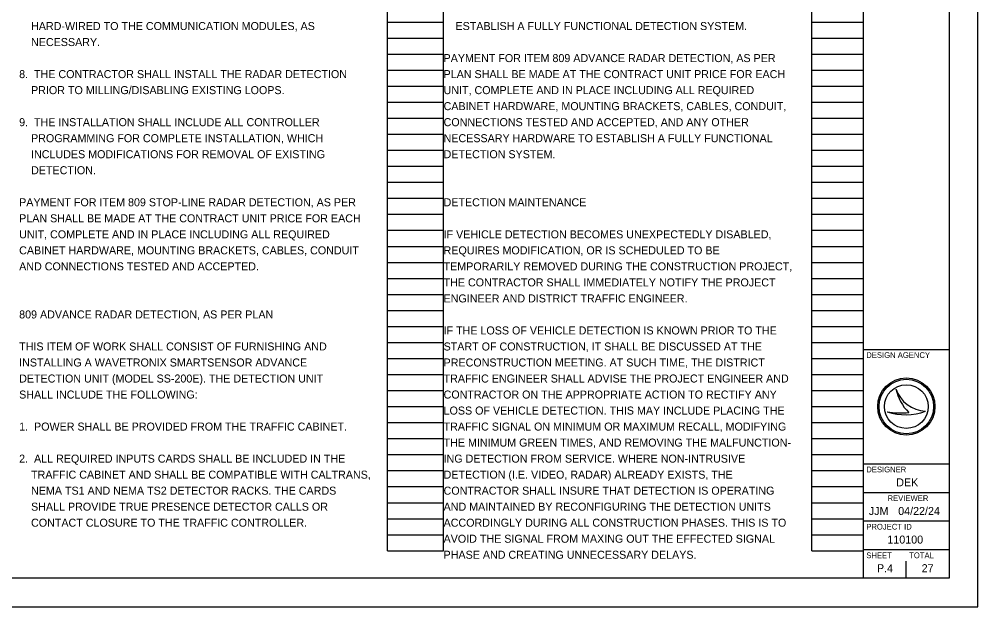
# Model space of a CAD drawing. Extents: x 0 to 34, y 0 to 22.
# Drawn here: x 17.24 to 34, y 0 to 10.27 of the extents above; entities that cross this region are included whole.
import ezdxf

# ---------------------------------------------------------------- set-up
doc = ezdxf.new("R2010")
doc.units = 0
for name, color, linetype in [('SH_Border', 7, 'Continuous'), ('SH_Cut_Line', 7, 'Continuous'), ('SH_Data', 7, 'Continuous'), ('SH_Text', 7, 'Continuous')]:
    doc.layers.add(name, color=color, linetype=linetype)

msp = doc.modelspace()

# ---------------------------------------------------------------- linework, layer by layer
at = {"layer": 'SH_Border'}
for p, q in [((32, 0.5), (32, 21.5)), ((32, 4.5), (33.5, 4.5)), ((32, 2.5), (33.5, 2.5)), ((32, 2), (33.5, 2)), ((32, 1.5), (33.5, 1.5)), ((32, 1), (33.5, 1))]:
    msp.add_line(p, q, dxfattribs=at)
msp.add_lwpolyline([(1.5, 21.5), (33.5, 21.5), (33.5, 0.5), (1.5, 0.5)], close=True, dxfattribs=at)
at = {"layer": 'SH_Cut_Line'}
msp.add_lwpolyline([(0, 0), (34, 0), (34, 22), (0, 22)], close=True, dxfattribs=at)
at = {"layer": 'SH_Data'}
for p, q in [((23.68, 0.98), (23.68, 21.14)), ((24.66, 0.98), (24.66, 21.14)), ((31.1, 0.98), (31.1, 21.14)), ((32, 0.98), (32, 21.14)), ((23.68, 10.22), (24.66, 10.22)), ((31.1, 10.22), (32, 10.22)), ((23.68, 9.94), (24.66, 9.94)), ((31.1, 9.94), (32, 9.94)), ((23.68, 9.66), (24.66, 9.66)), ((31.1, 9.66), (32, 9.66)), ((23.68, 9.38), (24.66, 9.38)), ((31.1, 9.38), (32, 9.38)), ((23.68, 9.1), (24.66, 9.1)), ((31.1, 9.1), (32, 9.1)), ((23.68, 8.82), (24.66, 8.82)), ((31.1, 8.82), (32, 8.82)), ((23.68, 8.54), (24.66, 8.54)), ((31.1, 8.54), (32, 8.54)), ((23.68, 8.26), (24.66, 8.26)), ((31.1, 8.26), (32, 8.26)), ((23.68, 7.98), (24.66, 7.98)), ((31.1, 7.98), (32, 7.98)), ((23.68, 7.7), (24.66, 7.7)), ((31.1, 7.7), (32, 7.7)), ((23.68, 7.42), (24.66, 7.42)), ((31.1, 7.42), (32, 7.42)), ((23.68, 7.14), (24.66, 7.14)), ((31.1, 7.14), (32, 7.14)), ((23.68, 6.86), (24.66, 6.86)), ((31.1, 6.86), (32, 6.86)), ((23.68, 6.58), (24.66, 6.58)), ((31.1, 6.58), (32, 6.58)), ((23.68, 6.3), (24.66, 6.3)), ((31.1, 6.3), (32, 6.3)), ((23.68, 6.02), (24.66, 6.02)), ((31.1, 6.02), (32, 6.02)), ((23.68, 5.74), (24.66, 5.74)), ((31.1, 5.74), (32, 5.74)), ((23.68, 5.46), (24.66, 5.46)), ((31.1, 5.46), (32, 5.46)), ((23.68, 5.18), (24.66, 5.18)), ((31.1, 5.18), (32, 5.18)), ((23.68, 4.9), (24.66, 4.9)), ((31.1, 4.9), (32, 4.9)), ((23.68, 4.62), (24.66, 4.62)), ((31.1, 4.62), (32, 4.62)), ((23.68, 4.34), (24.66, 4.34)), ((31.1, 4.34), (32, 4.34)), ((23.68, 4.06), (24.66, 4.06)), ((31.1, 4.06), (32, 4.06)), ((23.68, 3.78), (24.66, 3.78)), ((31.1, 3.78), (32, 3.78)), ((32.567, 3.81), (32.567, 3.81)), ((23.68, 3.5), (24.66, 3.5)), ((31.1, 3.5), (32, 3.5)), ((32.417, 3.41), (32.417, 3.41)), ((32.75, 3.5), (32.75, 3.5)), ((33.087, 3.419), (33.087, 3.419)), ((23.68, 3.22), (24.66, 3.22)), ((31.1, 3.22), (32, 3.22)), ((23.68, 2.94), (24.66, 2.94)), ((31.1, 2.94), (32, 2.94)), ((23.68, 2.66), (24.66, 2.66)), ((31.1, 2.66), (32, 2.66)), ((23.68, 2.38), (24.66, 2.38)), ((31.1, 2.38), (32, 2.38)), ((23.68, 2.1), (24.66, 2.1)), ((31.1, 2.1), (32, 2.1)), ((23.68, 1.82), (24.66, 1.82)), ((31.1, 1.82), (32, 1.82)), ((23.68, 1.54), (24.66, 1.54)), ((31.1, 1.54), (32, 1.54)), ((23.68, 1.26), (24.66, 1.26)), ((31.1, 1.26), (32, 1.26)), ((23.68, 0.98), (24.66, 0.98)), ((31.1, 0.98), (32, 0.98)), ((32.375, 0.675), (32.375, 0.675)), ((32.75, 0.5), (32.75, 0.8))]:
    msp.add_line(p, q, dxfattribs=at)
for radius in [0.5, 0.477, 0.477, 0.382]:
    msp.add_circle((32.75, 3.5), radius, dxfattribs=at)
for centre, radius, start, end in [((33.116, 3.998), 0.58, 198.9257, 198.9319), ((33.347, 3.97), 0.796, 191.6379, 191.6421), ((33.116, 3.998), 0.58, 198.9319, 267.1657), ((33.347, 3.97), 0.796, 191.6421, 226.0947), ((32.739, 4.37), 1.013, 251.4576, 290.0832), ((32.648, 4.654), 1.266, 259.4964, 259.4995), ((32.739, 4.37), 1.013, 251.4527, 251.4576), ((32.648, 4.654), 1.266, 259.4995, 276.6672)]:
    msp.add_arc(centre, radius, start, end, dxfattribs=at)

# ---------------------------------------------------------------- texts
for s, height, p in [('DESIGN AGENCY', 0.1, (32.05, 4.35)), ('DESIGNER', 0.1, (32.05, 2.35)), ('DEK', 0.14, (32.574, 2.105)), ('REVIEWER', 0.1, (32.422, 1.85)), ('JJM', 0.14, (32.095, 1.605)), ('04/22/24', 0.14, (32.608, 1.605)), ('PROJECT ID', 0.1, (32.05, 1.35)), ('110100', 0.14, (32.419, 1.105)), ('SHEET', 0.1, (32.05, 0.85)), ('TOTAL', 0.1, (32.8, 0.85)), ('P.4', 0.14, (32.237, 0.605)), ('27', 0.14, (33.018, 0.605))]:
    msp.add_text(s, height=height, dxfattribs=at).set_placement(p)
at = {"layer": 'SH_Text'}
for s, p in [('    HARD-WIRED TO THE COMMUNICATION MODULES, AS', (17.24, 10.08)), ('    ESTABLISH A FULLY FUNCTIONAL DETECTION SYSTEM.', (24.66, 10.08)), ('    NECESSARY.', (17.24, 9.8)), ('PAYMENT FOR ITEM 809 ADVANCE RADAR DETECTION, AS PER', (24.66, 9.52)), ('8.  THE CONTRACTOR SHALL INSTALL THE RADAR DETECTION', (17.24, 9.24)), ('PLAN SHALL BE MADE AT THE CONTRACT UNIT PRICE FOR EACH', (24.66, 9.24)), ('    PRIOR TO MILLING/DISABLING EXISTING LOOPS.', (17.24, 8.96)), ('UNIT, COMPLETE AND IN PLACE INCLUDING ALL REQUIRED', (24.66, 8.96)), ('CABINET HARDWARE, MOUNTING BRACKETS, CABLES, CONDUIT,', (24.66, 8.68)), ('9.  THE INSTALLATION SHALL INCLUDE ALL CONTROLLER', (17.24, 8.4)), ('CONNECTIONS TESTED AND ACCEPTED, AND ANY OTHER', (24.66, 8.4)), ('    PROGRAMMING FOR COMPLETE INSTALLATION, WHICH', (17.24, 8.12)), ('NECESSARY HARDWARE TO ESTABLISH A FULLY FUNCTIONAL', (24.66, 8.12)), ('    INCLUDES MODIFICATIONS FOR REMOVAL OF EXISTING', (17.24, 7.84)), ('DETECTION SYSTEM.', (24.66, 7.84)), ('    DETECTION.', (17.24, 7.56)), ('PAYMENT FOR ITEM 809 STOP-LINE RADAR DETECTION, AS PER', (17.24, 7)), ('DETECTION MAINTENANCE', (24.66, 7)), ('PLAN SHALL BE MADE AT THE CONTRACT UNIT PRICE FOR EACH', (17.24, 6.72)), ('UNIT, COMPLETE AND IN PLACE INCLUDING ALL REQUIRED', (17.24, 6.44)), ('IF VEHICLE DETECTION BECOMES UNEXPECTEDLY DISABLED,', (24.66, 6.44)), ('CABINET HARDWARE, MOUNTING BRACKETS, CABLES, CONDUIT', (17.24, 6.16)), ('REQUIRES MODIFICATION, OR IS SCHEDULED TO BE', (24.66, 6.16)), ('AND CONNECTIONS TESTED AND ACCEPTED.', (17.24, 5.88)), ('TEMPORARILY REMOVED DURING THE CONSTRUCTION PROJECT,', (24.66, 5.88)), ('THE CONTRACTOR SHALL IMMEDIATELY NOTIFY THE PROJECT', (24.66, 5.6)), ('ENGINEER AND DISTRICT TRAFFIC ENGINEER.', (24.66, 5.32)), ('809 ADVANCE RADAR DETECTION, AS PER PLAN', (17.24, 5.04)), ('IF THE LOSS OF VEHICLE DETECTION IS KNOWN PRIOR TO THE', (24.66, 4.76)), ('THIS ITEM OF WORK SHALL CONSIST OF FURNISHING AND', (17.24, 4.48)), ('START OF CONSTRUCTION, IT SHALL BE DISCUSSED AT THE', (24.66, 4.48)), ('INSTALLING A WAVETRONIX SMARTSENSOR ADVANCE', (17.24, 4.2)), ('PRECONSTRUCTION MEETING. AT SUCH TIME, THE DISTRICT', (24.66, 4.2)), ('DETECTION UNIT (MODEL SS-200E). THE DETECTION UNIT', (17.24, 3.92)), ('TRAFFIC ENGINEER SHALL ADVISE THE PROJECT ENGINEER AND', (24.66, 3.92)), ('SHALL INCLUDE THE FOLLOWING:', (17.24, 3.64)), ('CONTRACTOR ON THE APPROPRIATE ACTION TO RECTIFY ANY', (24.66, 3.64)), ('LOSS OF VEHICLE DETECTION. THIS MAY INCLUDE PLACING THE', (24.66, 3.36)), ('1.  POWER SHALL BE PROVIDED FROM THE TRAFFIC CABINET.', (17.24, 3.08)), ('TRAFFIC SIGNAL ON MINIMUM OR MAXIMUM RECALL, MODIFYING', (24.66, 3.08)), ('THE MINIMUM GREEN TIMES, AND REMOVING THE MALFUNCTION-', (24.66, 2.8)), ('2.  ALL REQUIRED INPUTS CARDS SHALL BE INCLUDED IN THE', (17.24, 2.52)), ('ING DETECTION FROM SERVICE. WHERE NON-INTRUSIVE', (24.66, 2.52)), ('    TRAFFIC CABINET AND SHALL BE COMPATIBLE WITH CALTRANS,', (17.24, 2.24)), ('DETECTION (I.E. VIDEO, RADAR) ALREADY EXISTS, THE', (24.66, 2.24)), ('    NEMA TS1 AND NEMA TS2 DETECTOR RACKS. THE CARDS', (17.24, 1.96)), ('CONTRACTOR SHALL INSURE THAT DETECTION IS OPERATING', (24.66, 1.96)), ('    SHALL PROVIDE TRUE PRESENCE DETECTOR CALLS OR', (17.24, 1.68)), ('AND MAINTAINED BY RECONFIGURING THE DETECTION UNITS', (24.66, 1.68)), ('    CONTACT CLOSURE TO THE TRAFFIC CONTROLLER.', (17.24, 1.4)), ('ACCORDINGLY DURING ALL CONSTRUCTION PHASES. THIS IS TO', (24.66, 1.4)), ('AVOID THE SIGNAL FROM MAXING OUT THE EFFECTED SIGNAL', (24.66, 1.12)), ('PHASE AND CREATING UNNECESSARY DELAYS.', (24.66, 0.84))]:
    msp.add_text(s, height=0.14, dxfattribs=at).set_placement(p)

doc.saveas('drawing.dxf')
